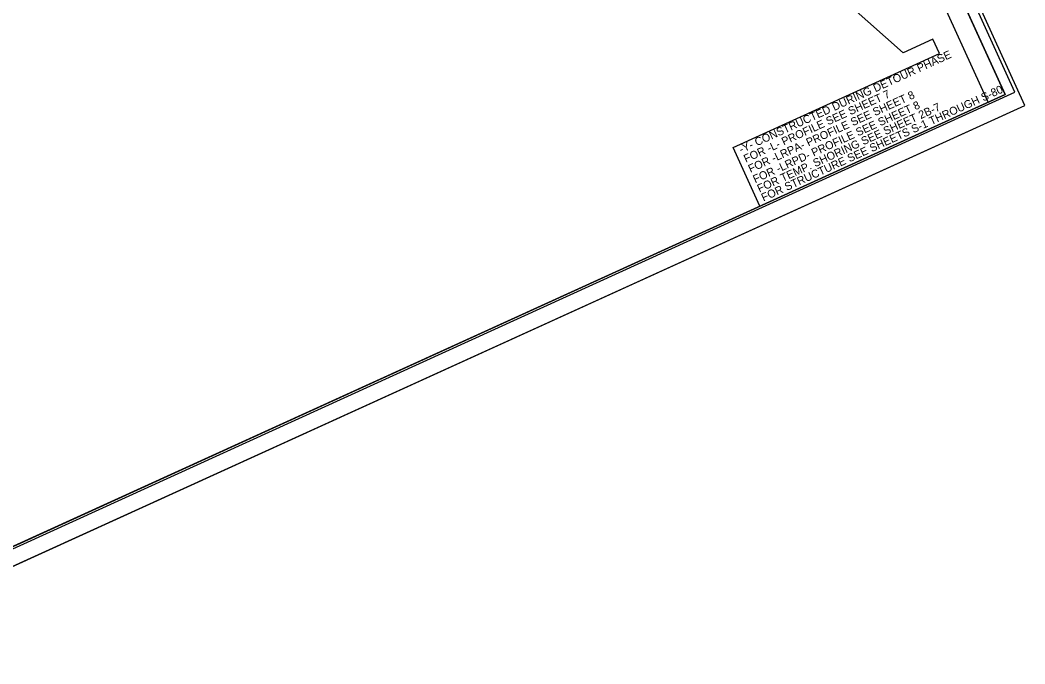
# Model space of a CAD drawing. Extents: x 2247864 to 2249896, y 662531 to 664296.
# Drawn here: x 2248641 to 2249896, y 662531 to 663336 of the extents above; entities that cross this region are included whole.
import ezdxf

# ---------------------------------------------------------------- set-up
doc = ezdxf.new("R2010")
doc.units = 0
for name, color, linetype in [('Prop Dimension', 7, 'Continuous'), ('Sheet Clip Boundary CELL', 7, 'Continuous'), ('Sheet Cutting Line CELL', 7, 'Continuous'), ('Sheet Layout Plan Border', 7, 'Continuous'), ('Sheet Plan CELL', 7, 'Continuous'), ('Sheet Plan Layout CELL', 7, 'Continuous'), ('Sheet Plot Border Inside CELL', 7, 'Continuous'), ('Sheet Plot Border Outside CELL', 7, 'Continuous')]:
    doc.layers.add(name, color=color, linetype=linetype)

msp = doc.modelspace()

# ---------------------------------------------------------------- linework, layer by layer
at = {"layer": 'Sheet Clip Boundary CELL'}
msp.add_lwpolyline([(2248241.7, 663371.1), (2248514.4, 662770.6), (2248551.2, 662641.6), (2249564.6, 663103.3), (2249531.2, 663176.6), (2249788.9, 663294.1), (2249780.7, 663312.1), (2249743.4, 663294.9), (2249677.4, 663353.6), (2249425.3, 663908.7), (2249477.5, 663985.1), (2249305.3, 663906.7), (2249217.6, 664099.1), (2248115.8, 663597.1)], close=True, dxfattribs=at)
at = {"layer": 'Sheet Cutting Line CELL'}
msp.add_line((2248363.6, 662531.3), (2249895.5, 663229.4), dxfattribs=at)
at = {"layer": 'Sheet Layout Plan Border'}
msp.add_lwpolyline([(2248198.1, 663481.5), (2248575.8, 662652.8), (2249849.7, 663233.3), (2249502.1, 663996.3), (2249329.8, 663917.8), (2249242.1, 664110.3), (2248140.4, 663608.2)], close=True, dxfattribs=at)
at = {"layer": 'Sheet Plan CELL'}
for points in [[(2249435.3, 664198.3), (2248070.3, 663576.3), (2248505.7, 662620.9), (2249870.7, 663242.8)], [(2248505.7, 662620.9), (2248070.3, 663576.3), (2249253.3, 664115.4), (2249315.5, 663978.8), (2249497.5, 664061.8), (2249870.7, 663242.8)]]:
    msp.add_lwpolyline(points, close=True, dxfattribs=at)
at = {"layer": 'Sheet Plan Layout CELL'}
msp.add_lwpolyline([(2248070.3, 663576.3), (2248505.7, 662620.9), (2249870.7, 663242.8), (2249523, 664005.9), (2249305.3, 663906.7), (2249217.6, 664099.1)], close=True, dxfattribs=at)
at = {"layer": 'Sheet Plot Border Inside CELL'}
msp.add_lwpolyline([(2248367.1, 662554.9), (2249883.1, 663245.8), (2249445.6, 664205.8), (2247929.6, 663514.9)], close=True, dxfattribs=at)
at = {"layer": 'Sheet Plot Border Outside CELL'}
msp.add_lwpolyline([(2248363.6, 662531.3), (2249895.5, 663229.4), (2249441.4, 664225.8), (2247909.5, 663527.8)], close=True, dxfattribs=at)

# ---------------------------------------------------------------- texts
at = {"layer": 'Prop Dimension'}
for s, p in [('-Y- CONSTRUCTED DURING DETOUR PHASE', (2249541.1, 663169.3)), ('FOR STRUCTURE SEE SHEETS S-1 THROUGH S-80', (2249569, 663109.1)), ('FOR -L- PROFILE SEE SHEET 7', (2249547, 663157.5)), ('FOR -LRPA- PROFILE SEE SHEET 8', (2249552.7, 663145)), ('FOR -LRPD- PROFILE SEE SHEET 8', (2249558.6, 663132)), ('FOR TEMP. SHORING SEE SHEET 2B-7', (2249563.9, 663120.3))]:
    msp.add_text(s, height=10, rotation=24.4979, dxfattribs=at).set_placement(p)

doc.saveas('drawing.dxf')
